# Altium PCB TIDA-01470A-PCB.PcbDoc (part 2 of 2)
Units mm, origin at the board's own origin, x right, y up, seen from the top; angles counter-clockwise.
Board outline 75 x 58 mm, 6 copper layers (Top Copper, Copper Layer 2, Copper Layer 3, Copper Layer 4, Copper Layer 5, Bottom Copper), stack 1.56 mm thick; 131 components, 70 nets, 308 pads, 94 vias.
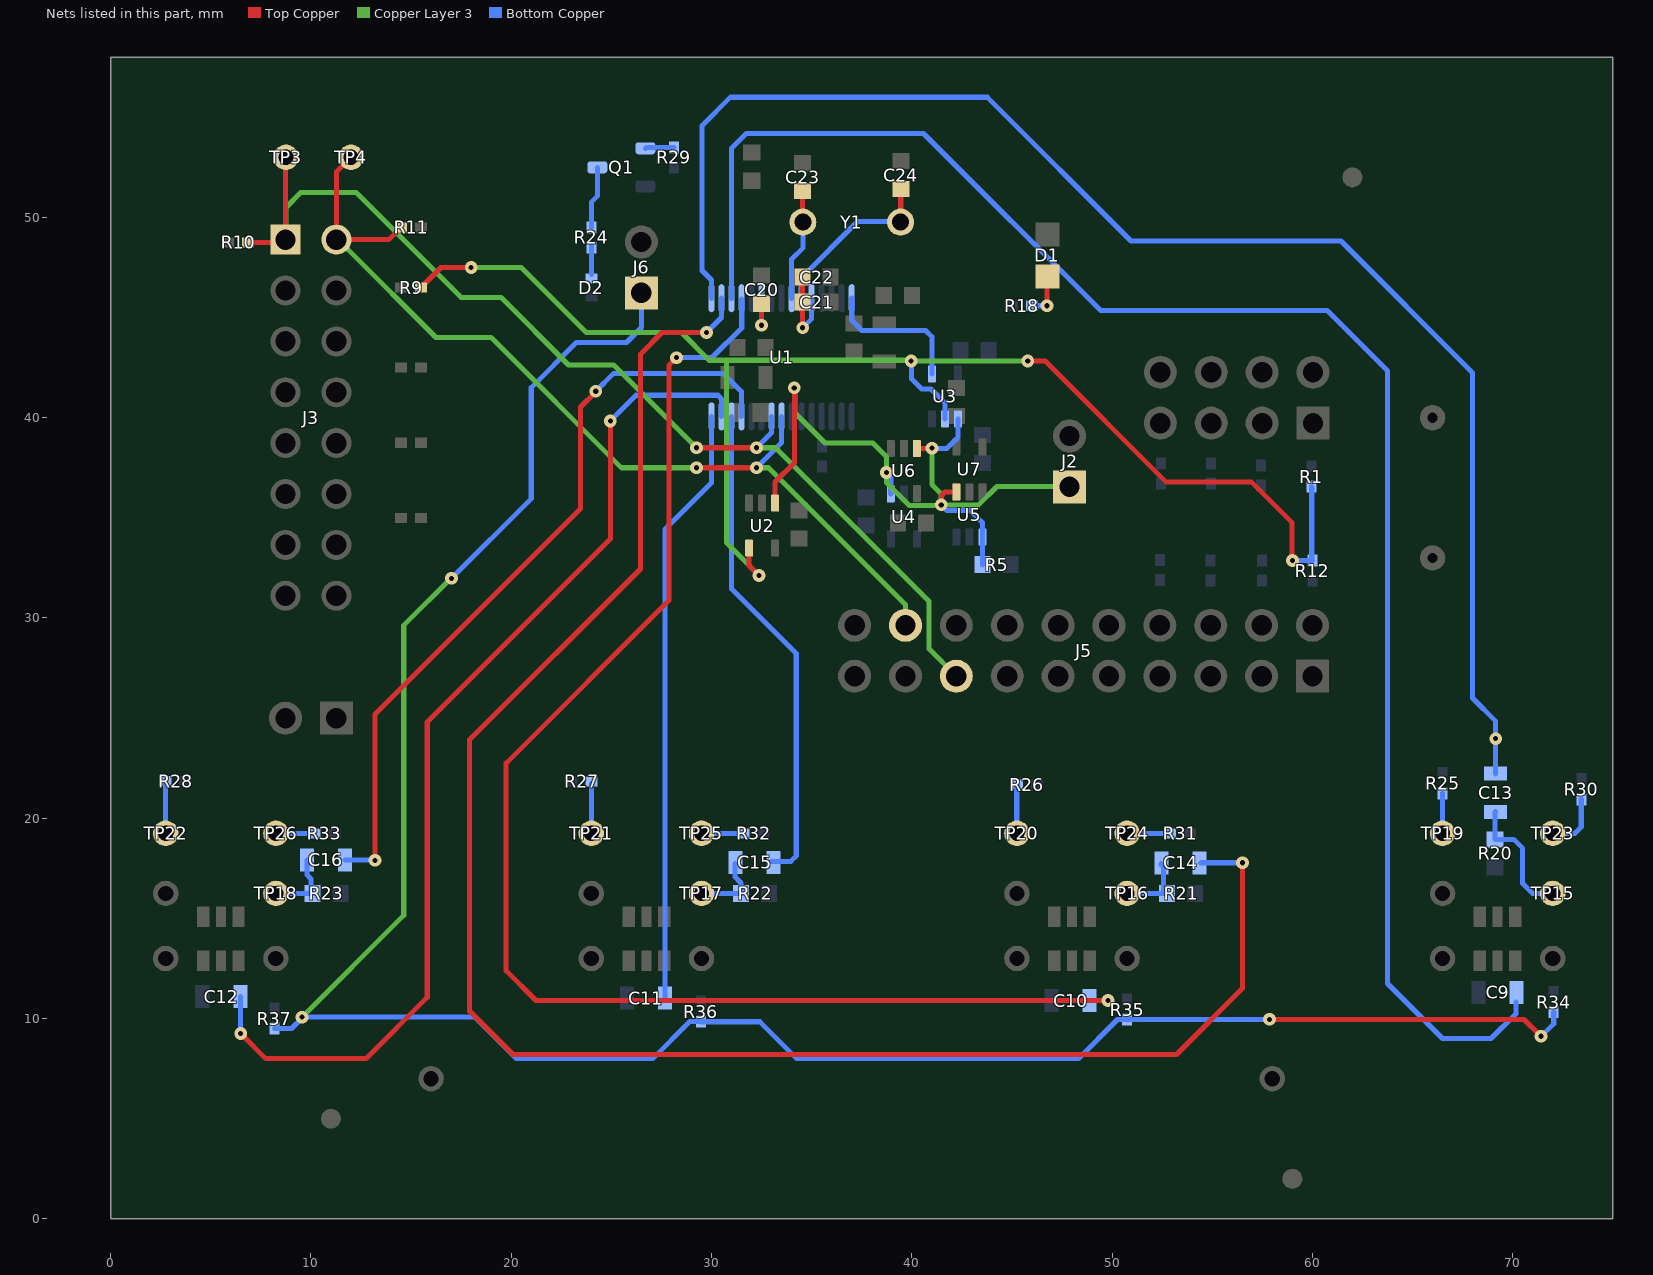
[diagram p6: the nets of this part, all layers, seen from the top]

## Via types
v1: diameter 0.635, hole 0.254, Top Copper to Bottom Copper, tented both sides, 86 vias
v2: diameter 6, hole 3.25, Top Copper to Bottom Copper, tented both sides, 4 vias
v3: diameter 0.762, hole 0.381, Top Copper to Bottom Copper, tented both sides, 4 vias

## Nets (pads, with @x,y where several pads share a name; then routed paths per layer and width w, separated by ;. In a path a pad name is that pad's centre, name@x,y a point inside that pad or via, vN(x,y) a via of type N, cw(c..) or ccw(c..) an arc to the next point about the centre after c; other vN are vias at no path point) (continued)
NetC13_2: C13.2 R20.1 TP15.1 | length 6.4
  Bottom Copper w0.254: C13.2@69.15,20.325 69.125,20.3 R20.1@69.125,18.95 70.05,18.95 70.5,18.5 70.5,16.75 71,16.25 TP15.1@72,16.25
NetC14_2: C14.2 R21.1 TP16.1 | length 3.6
  Bottom Copper w0.254: TP16.1@50.725,16.2 50.775,16.25 R21.1@52.75,16.25 52.575,16.425 C14.2@52.575,17.675 ; C14.2@52.45,17.675 C14.2@52.45,17.75
NetC15_2: C15.2 R22.1 TP17.1 | length 3.7
  Bottom Copper w0.254: TP17.1@29.45,16.225 29.475,16.25 TP17.1@29.5,16.25 R22.1@31.475,16.25 31.475,16.775 31.175,17.075 C15.2@31.175,17.75
NetC16_2: C16.2 R23.1 TP18.1 | length 3.6
  Bottom Copper w0.254: TP18.1@8.25,16.2 8.3,16.25 R23.1@10.075,16.25 ; C16.2@9.8,17.925 9.8,17.175 10,16.975 R23.1@10,16.275
NetC20_1: C20.1 U1.6 | length 2.4
  Top Copper w0.254: v1@32.5,44.64 C20.1@32.5,45.69
  Bottom Copper w0.254: v1(32.5,44.615) U1.6@32.5,45.965
NetC21_2: C21.2 C22.1 U1.11 | length 4.1
  Top Copper w0.254: v1@34.55,44.515 C21.2@34.55,45.765 ; C21.2@34.55,45.815 C22.1@34.55,47.015
  Bottom Copper w0.254: v1(34.55,44.49) 35,44.94 U1.11@35,45.965
NetC23_1: C23.1 U1.9 Y1.1 | length 5.6
  Top Copper w0.254: Y1.1@34.55,49.815 C23.1@34.55,51.315
  Bottom Copper w0.254: U1.9@34.023,45.988 U1.9@34,45.965 34,47.91 34.575,48.485 Y1.1@34.575,49.74 ; Y1.1@34.55,49.765 Y1.1@34.575,49.74 ; Y1.1@34.55,49.79 34.575,49.765 Y1.1@34.575,49.74
NetC24_1: C24.1 U1.10 Y1.2 | length 8.8
  Top Copper w0.254: Y1.2@39.45,49.715 C24.1@39.45,51.415
  Bottom Copper w0.254: U1.10@34.5,45.965 34.5,47 37.29,49.79 Y1.2@39.425,49.79
NetD1_1: D1.1 R18.1 | length 2
  Top Copper w0.254: v1(46.75,45.59) D1.1@46.75,47.09
  Bottom Copper w0.254: R18.1@46.25,45.59 v1(46.75,45.59)
NetD2_2: D2.2 R24.1 | length 1.5
  Bottom Copper w0.254: D2.2@24,47.15 R24.1@24,48.65
NetJ2_1: J2.1 R5.1 U2.1 U3.1 U4.1 U5.1 U6.1 U7.1 | length 37.2
  Top Copper w0.254: U2.1@33.175,35.74 33.175,36.785 34.15,37.76 v1@34.15,41.5 ; U6.1@40.25,38.465 v1@40.935,38.465 ; v1@41.48,35.63 41.48,36.12 41.65,36.29 U7.1@42.225,36.29
  Copper Layer 3 w0.254: v1(34.13,41.49) 34.13,41.479 34.17,41.439 34.17,40.24 35.67,38.74 38.05,38.74 38.73,38.06 38.73,36.76 39.87,35.62 v1@41.42,35.62 ; v1@41,38.46 41,36.66 41.47,36.19 v1(41.47,35.65) 43.34,35.65 44.25,36.56 J2.1@47.83,36.56
  Bottom Copper w0.254: v1@38.72,37.25 38.95,37.02 U4.1@38.95,36.19 ; v1@41.03,38.47 41.76,38.47 42.3,39.01 U3.1@42.3,39.94 ; v1@41.48,35.64 41.76,35.36 42.92,35.36 43.525,34.755 U5.1@43.525,34.04 43.525,32.645 R5.1@43.53,32.64
  other v1: 38.73,37.26 41.01,38.48
NetJ6_1: J6.1 R34.1 R35.1 R36.1 R37.1 | length 112.8
  Top Copper w0.254: v1(57.86,9.96) 70.57,9.96 v1(71.41,9.12)
  Copper Layer 3 w0.254: v1(9.55,10.07) 14.634,15.154 14.634,29.634 v1@17,32
  Bottom Copper w0.254: R37.1@8.175,9.5 9.03,9.5 v1@9.54,10.01 ; v1(9.55,10.07) 18.18,10.07 20.25,8 27.07,8 28.92,9.85 R36.1@29.39,9.85 ; v1(17.02,31.98) 21,35.96 21,41.5 23.25,43.75 25.75,43.75 26.5,44.5 J6.1@26.5,46 ; R36.1@29.47,9.84 32.41,9.84 34.25,8 48.32,8 50.27,9.95 R35.1@50.75,9.95 R35.1@50.79,9.95 ; R35.1@50.78,9.94 R35.1@50.79,9.95 ; v1(57.86,9.96) 50.8,9.96 R35.1@50.79,9.95 ; v1@71.43,9.12 72.05,9.74 R34.1@72.05,10.32 ; R34.1@72.03,10.32 R34.1@72.04,10.31
NetQ1_1: Q1.1 R29.1 | length 1.4
  Bottom Copper w0.254: Q1.1@26.7,53.45 26.75,53.5 R29.1@28.125,53.5
NetQ1_3: Q1.3 R24.2 | length 3.1
  Bottom Copper w0.254: R24.2@24,49.5 24,50.76 24.3,51.06 Q1.3@24.3,52.5
NetR25_2: R25.2 TP19.1 | length 2.1
  Bottom Copper w0.254: TP19.1@66.475,19.3 66.525,19.25 TP19.1@66.525,19.175 ; TP19.1@66.5,19.25 R25.2@66.5,21.25
NetR26_2: R26.2 TP20.1 | length 2.5
  Bottom Copper w0.254: TP20.1@45.175,19.25 45.24,19.315 45.24,21.665 R26.2@45.25,21.675
NetR27_2: R27.2 TP21.1 | length 2.4
  Bottom Copper w0.254: TP21.1@23.95,19.325 24,19.375 R27.2@24,21.75
NetR28_2: R28.2 TP22.1 | length 2.6
  Bottom Copper w0.254: R28.2@2.75,21.85 2.75,19.3 TP22.1@2.775,19.275
NetR30_2: R30.2 TP23.1 | length 2.9
  Bottom Copper w0.254: TP23.1@72.05,19.25 73.11,19.25 73.425,19.565 R30.2@73.425,20.95
NetR31_2: R31.2 TP24.1 | length 2.2
  Bottom Copper w0.254: TP24.1@50.725,19.25 TP24.1@50.75,19.25 R31.2@52.9,19.25
NetR32_2: R32.2 TP25.1 | length 2.1
  Bottom Copper w0.254: TP25.1@29.5,19.225 29.525,19.25 R32.2@31.6,19.25
NetR33_2: R33.2 TP26.1 | length 1.9
  Bottom Copper w0.254: TP26.1@8.25,19.25 10.125,19.25 R33.2@10.15,19.225
SCK: R1.1 R9.1 R12.1 U2.4 U3.2 | length 72.4
  Top Copper w0.254: R9.1@15.5,46.5 16.5,47.5 v1(18,47.5) ; U2.4@31.875,33.49 31.875,32.605 v1@32.34,32.14 ; v1@45.8,42.83 46.66,42.83 52.71,36.78 56.97,36.78 58.99,34.76 58.99,32.89 v1(59.01,32.87)
  Copper Layer 3 w0.254: v1(18,47.5) 20.5,47.5 23.75,44.25 28.5,44.25 29.88,42.87 30.75,42.87 ; v1@32.29,32.2 32.29,32.22 30.75,33.76 30.75,42.87 ; v1@39.91,42.85 39.89,42.87 30.75,42.87 ; v1(39.97,42.83) v1(45.79,42.83)
  Bottom Copper w0.254: v1@39.99,42.79 39.99,41.94 40.492,41.438 40.962,41.438 41.65,40.75 U3.2@41.65,39.94 ; v1@58.995,32.865 R12.1@59.955,32.865 ; R1.1@59.955,36.56 59.97,36.545 59.97,32.865 R12.1@60,32.865
  other v1: 32.37,32.12
SCKIA: U1.15 U3.4 | length 7.3
  Bottom Copper w0.254: U1.15@37,45.965 37,44.86 37.5,44.36 40.68,44.36 41,44.04 U3.4@41,42.19
SCL: J3.1 J5.15 R10.2 TP3.1 U1.24 | length 54.2
  Top Copper w0.254: R10.2@6.87,48.75 J3.1@8.35,48.75 ; J3.1@8.73,48.89 8.73,52.98 TP3.1@8.75,53 ; TP3.1@9,53 TP3.1@9.02,53.02 ; v1(29.25,38.5) 30.75,38.5 v1(32.25,38.5)
  Copper Layer 3 w0.254: J3.1@8.75,49 8.75,50.5 9.5,51.25 12.25,51.25 17.5,46 19.5,46 22.866,42.634 25.116,42.634 v1(29.25,38.5) ; v1(32.25,38.5) 33.2,38.5 40.86,30.84 40.86,28.46 J5.15@42.225,27.095
  Bottom Copper w0.254: v1(32.25,38.5) 33,39.25 33,39.5 U1.24@33,40.065
SDA: J3.2 J5.18 R11.2 TP4.1 U1.23 | length 47.1
  Top Copper w0.254: J3.2@11.27,48.89 11.27,52.27 TP4.1@12,53 ; J3.2@11.5,48.75 11.64,48.89 13.89,48.89 R11.2@14.5,49.5 ; TP4.1@12.25,53 TP4.1@12.27,52.98 ; v1(29.25,37.5) v1(32.25,37.5)
  Copper Layer 3 w0.254: J3.2@11.815,48.435 16.25,44 19,44 25.5,37.5 v1(29.25,37.5) ; v1(32.25,37.5) 32.85,37.5 39.685,30.665 J5.18@39.685,29.635
  Bottom Copper w0.254: v1(32.25,37.5) 33.5,38.75 U1.23@33.5,40.065
VIN1M: C13.1 U1.1 | length 74.2
  Copper Layer 3 w0.254: v1@69.07,23.91 v1@69.12,23.96 ; v1@69.1,23.925 v1@69.125,23.95
  Bottom Copper w0.254: U1.1@30,45.965 30,46.87 29.52,47.35 29.52,54.58 30.94,56 43.77,56 50.95,48.82 61.43,48.82 68,42.25 68,26 69.15,24.85 v1(69.15,23.975) C13.1@69.15,22.225
VIN1P: C9.1 U1.3 | length 84.7
  Bottom Copper w0.254: U1.3@31,45.965 31,53.45 31.74,54.19 40.59,54.19 49.43,45.35 60.74,45.35 63.75,42.34 63.75,11.75 66.5,9 68.92,9 70.16,10.24 70.16,10.81 C9.1@70.175,10.825
VIN2M: C14.1 U1.2 | length 91.1
  Top Copper w0.254: v1(29.75,44.25) 27.53,44.25 26.45,43.17 26.45,32.45 17.92,23.92 17.92,10.38 20.09,8.21 53.21,8.21 56.51,11.51 v1(56.51,17.78)
  Bottom Copper w0.254: v1@29.899,44.399 30.5,45 U1.2@30.5,45.965 ; C14.1@54.41,17.76 54.43,17.78 v1(56.51,17.78)
VIN2P: C10.1 U1.4 | length 70.9
  Top Copper w0.254: v1(28.25,43) 27.87,42.62 27.87,30.87 19.75,22.75 19.75,12.39 21.24,10.9 v1(49.8,10.9)
  Bottom Copper w0.254: v1(28.25,43) 30.03,43 31.51,44.48 31.51,45.91 U1.4@31.49,45.93 ; C10.1@48.875,10.9 v1@49.69,10.9
VIN3M: C15.1 U1.28 | length 24.6
  Bottom Copper w0.254: U1.28@31,40.065 31,31.456 34.23,28.226 34.23,18.12 33.96,17.85 C15.1@32.99,17.85
VIN3P: C11.1 U1.30 | length 30
  Bottom Copper w0.254: C11.1@27.675,11.025 27.675,34.425 30,36.75 U1.30@30,40.05
VIN4M: C16.1 U1.27 | length 38.7
  Top Copper w0.254: v1(13.2,17.9) 13.2,25.2 23.46,35.46 23.46,40.53 24.23,41.3 v1@24.23,41.33
  Bottom Copper w0.254: C16.1@11.7,17.925 v1@13.13,17.92 ; v1@24.23,41.33 25.1,42.2 30.6,42.2 31.5,41.3 31.5,40.88 U1.27@31.5,40.065 U1.27@31.477,40.088
  other v1: 24.22,41.32
VIN4P: C12.1 U1.29 | length 52.5
  Top Copper w0.254: v1@6.56,9.19 7.75,8 12.75,8 15.81,11.06 15.81,24.81 24.95,33.95 v1(24.95,39.84)
  Bottom Copper w0.254: C12.1@6.475,11.1 6.475,9.285 v1@6.51,9.25 ; v1(24.95,39.84) 26.23,41.12 30.32,41.12 30.5,40.94 U1.29@30.5,40.065
  other v1: 6.49,9.25
pads on no net: FID1.1 FID2.1 FID3.1 H1.0 H2.0 H3.0 H4.0 H5.0 H6.0 H7.0 H8.0 J3.5 J3.13 J3.14 SH1.0 SH2.0 U1.26

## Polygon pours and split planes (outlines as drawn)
GND on Copper Layer 5 "GND2" (solid, remove dead copper, pour order 38): 0,0 0,58 75,58 75,0
GND on Copper Layer 4 "COPPER_LAYER_4_GND_P042" (solid, remove dead copper, pour order 42): 0,0 0,58 75,58 75,0
3.3V on Copper Layer 4 "3.3V" (solid, remove dead copper, pour order 40): 68,12 65,9 8.575,9 4.5,13.075 4.5,50.333 5.667,51.5 20,51.5 25,56.5 55.5,56.5 68,44
GND on Bottom Copper "BOTTOM_COPPER_GND_P044" (solid, remove dead copper, pour order 44): 0,0 0,58 75,58 75,0
GND on Top Copper "TOP_COPPER_GND_P046" (solid, remove dead copper, pour order 46): 0,0 0,58 75,58 75,0
GND on Copper Layer 3 "COPPER_LAYER_3_GND_P048" (solid, remove dead copper, pour order 48): 0,0 0,58 75,58 75,-0.18 74.82,0
GND on Copper Layer 2 "GND1" (solid, remove dead copper, pour order 50): 75,58 75,0 0,0 0,58

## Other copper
Top Copper:
  text ".Layer_Name" at 2.156,-34.306 h1.52
Copper Layer 2:
  text ".Layer_Name" at 2.156,-34.306 h1.52
Copper Layer 3:
  text ".Layer_Name" at 2.156,-34.306 h1.52
Copper Layer 4:
  text ".Layer_Name" at 2.156,-34.306 h1.52
Copper Layer 5:
  text ".Layer_Name" at 2,-34.25 h1.52
Bottom Copper:
  text ".Layer_Name" at 2.156,-34.306 h1.52

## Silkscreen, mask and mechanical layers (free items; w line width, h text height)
Top SilkScreen:
  circle w0.254: c19,54 r3.25
  circle w0.254: c71,4 r3.25
  circle w0.254: c71,54 r3.25
  circle w0.254: c4,4 r3.25
  lines w0.2: 36.875,25.375 37.625,25.375 ; 37,25.125 37.5,25.125 ; 37.125,24.875 37.375,24.875 ; 37.25,25.375 37.25,25.75 ; 39.375,25.375 40.125,25.375 ; 39.5,25.125 40,25.125 ; 39.625,24.875 39.875,24.875 ; 39.75,25.375 39.75,25.75 ; 44.375,25.375 45.125,25.375 ; 44.375,31.625 45.125,31.625 ; 44.5,25.125 45,25.125 ; 44.5,31.375 45,31.375 ; 44.625,24.875 44.875,24.875 ; 44.625,31.125 44.875,31.125 ; 44.75,25.375 44.75,25.75 ; 44.75,31.625 44.75,32 ; 46.875,25.375 47.625,25.375 ; 47,25.125 47.5,25.125 ; 47.125,24.875 47.375,24.875 ; 47.25,25.375 47.25,25.75 ; 49.375,25.375 50.125,25.375 ; 49.375,31.625 50.125,31.625 ; 49.5,25.125 50,25.125 ; 49.5,31.375 50,31.375 ; 49.625,24.875 49.875,24.875 ; 49.625,31.125 49.875,31.125 ; 49.75,25.375 49.75,25.75 ; 49.75,31.625 49.75,32 ; 52.125,25.375 52.875,25.375 ; 52.25,25.125 52.75,25.125 ; 52.375,24.875 52.625,24.875 ; 52.5,25.375 52.5,25.75 ; 54.625,25.375 55.375,25.375 ; 54.75,25.125 55.25,25.125 ; 54.875,24.875 55.125,24.875 ; 55,25.375 55,25.75 ; 57.125,25.375 57.875,25.375 ; 57.25,25.125 57.75,25.125 ; 57.375,24.875 57.625,24.875 ; 57.5,25.375 57.5,25.75 ; 59.625,25.375 60.375,25.375 ; 59.75,25.125 60.25,25.125 ; 59.875,24.875 60.125,24.875 ; 60,25.375 60,25.75
  text "INTA" at 37.75,31 h1 r90
  text "SDA" at 40.25,31 h1 r90
  text "3.3V" at 42.75,31 h1 r90
  text "DATA3" at 47.75,31 h1 r90
  text "DATA1" at 53,31 h1 r90
  text "LRCLK" at 55.5,31 h1 r90
  text "BCLK" at 58,31 h1 r90
  text "MCLK" at 60.5,31 h1 r90
  text "'.EVM_Orderable'" at 12.5,27.5 h2
  text "'.PRJ_Number' '.PCB_Rev'" at 15.75,25 h1.6
  text "SCL" at 42.75,23.25 h1 r90
  text ".Layer_Name" at 2.156,-34.306 h1.52
Bottom Silk:
  lines w0.2: 36.875,25 37.625,25 ; 37,24.75 37.5,24.75 ; 37.125,24.5 37.375,24.5 ; 37.25,25 37.25,25.375 ; 39.375,25 40.125,25 ; 39.5,24.75 40,24.75 ; 39.625,24.5 39.875,24.5 ; 39.75,25 39.75,25.375 ; 44.375,25 45.125,25 ; 44.375,31.81 45.125,31.81 ; 44.5,24.75 45,24.75 ; 44.5,31.56 45,31.56 ; 44.625,24.5 44.875,24.5 ; 44.625,31.31 44.875,31.31 ; 44.75,25 44.75,25.375 ; 44.75,31.81 44.75,32 ; 46.875,25 47.625,25 ; 47,24.75 47.5,24.75 ; 47.125,24.5 47.375,24.5 ; 47.25,25 47.25,25.375 ; 49.375,25 50.125,25 ; 49.375,31.875 50.125,31.875 ; 49.5,24.75 50,24.75 ; 49.5,31.625 50,31.625 ; 49.625,24.5 49.875,24.5 ; 49.625,31.375 49.875,31.375 ; 49.75,25 49.75,25.375 ; 49.75,31.875 49.75,32.25 ; 52.125,25 52.875,25 ; 52.25,24.75 52.75,24.75 ; 52.375,24.5 52.625,24.5 ; 52.5,25 52.5,25.375 ; 54.625,25 55.375,25 ; 54.75,24.75 55.25,24.75 ; 54.875,24.5 55.125,24.5 ; 55,25 55,25.375 ; 57.125,25 57.875,25 ; 57.25,24.75 57.75,24.75 ; 57.375,24.5 57.625,24.5 ; 57.5,25 57.5,25.375 ; 59.625,25 60.375,25 ; 59.75,24.75 60.25,24.75 ; 59.875,24.5 60.125,24.5 ; 60,25 60,25.375
  text "GND" at 57.5,44.25 h1
  text "MASTER/ / SLAVE" at 50.5,40.875 h0.8
  text "2" at 63.25,40.125 h0.5
  text "I S" at 63.625,39.5 h1
  text "DATA1" at 51.5,38 h0.75 r90
  text "LRCLK" at 54,38 h0.75 r90
  text "BCLK" at 56.75,38 h0.75 r90
  text "MCLK" at 59.25,38 h0.75 r90
  text "DATA3" at 47.5,34 h0.6 r90
  text "LRCLK" at 54.375,33.75 h0.6 r90
  text "DATA" at 51.75,33.5 h0.6 r90
  text "BCLK" at 57,33.5 h0.6 r90
  text "MCLK" at 59.5,33.5 h0.6 r90
  text "3.3V" at 42.5,33.365 h0.75 r90
  text "INTA" at 37.5,33.25 h0.75 r90
  text "SDA" at 40,33.25 h0.75 r90
  text "SCL" at 42.75,25.36 h0.75 r90
  text ".Layer_Name" at 2.156,-34.306 h1.52
Top Paste:
  text ".Layer_Name" at 2.156,-34.306 h1.52
Bottom Paste:
  text ".Layer_Name" at 2.156,-34.306 h1.52
Top Solder Mask:
  text ".Layer_Name" at 2.156,-34.306 h1.52
Bottom Solder Mask:
  text ".Layer_Name" at 2.156,-34.306 h1.52
Drill Guide:
  text ".Layer_Name" at 82.5,25 h1.52
M1 Board Outline:
  the board outline again, w0.25
  text ".Layer_Name" at 44.25,-34.75 h1.52
M2 Board Dimensions:
  text ".Layer_Name" at 69.75,-34.75 h1.52
M3 3D STEP Top:
  text ".Layer_Name" at 2.156,-34.306 h1.52
M4 3D STEP Bottom:
  text ".Layer_Name" at 2.156,-34.306 h1.52
M5 Assembly Top:
  lines w0.254: -19.917,-36.126 147.723,-36.126 ; -19.917,-30.962 147.774,-30.962 ; -19.917,-25.797 -19.917,-41.291 81.81,-41.291 147.774,-41.291 147.774,-25.797 -19.904,-25.797 -19.904,-41.291 20.114,-41.291 ; 42.694,-41.291 42.694,-25.797 ; 74.876,-30.962 74.876,-25.797 ; 96.212,-30.962 96.212,-25.797 ; 112.011,-41.456 112.011,-36.304
  text "PCB VIEWED FROM TOP SIDE" at -18.304,-29.154 h1.52
  text "BOARD #:" at 44.599,-29.154 h1.52
  text ".PRJ_Number" at 58.455,-29.154 h1.52
  text "REV:" at 79.905,-29.154 h1.52
  text ".PCB_Rev" at 87.309,-29.154 h1.52
  text "SVN REV:" at 101.19,-29.154 h1.52
  text ".VersionControl_RevNumber" at 114.043,-29.154 h1.52
  text "PLOT NAME =" at -18.304,-39.534 h1.52
  text ".plot_File_Name" at 2.156,-39.534 h1.52
  text "GENERATED    :" at 44.65,-39.534 h1.52
  text ".Print_Date" at 66.735,-39.534 h1.52
  text ".Print_Time" at 85.252,-39.534 h1.52
  text "TEXAS INSTRUMENTS" at 117.37,-39.534 h1.52
M6 Assembly Bottom:
  lines w0.254: -19.93,-30.974 147.761,-30.974 ; -19.879,-36.139 147.761,-36.139 ; 15.834,-41.469 15.834,-36.317 ; 31.632,-30.974 31.632,-25.81 ; 52.968,-30.974 52.968,-25.81 ; 85.15,-41.304 85.15,-25.81 ; 107.731,-41.304 147.749,-41.304 147.749,-25.81 -19.93,-25.81 -19.93,-41.304 46.034,-41.304 147.761,-41.304 147.761,-25.81
  text ".VersionControl_RevNumber" at 13.802,-29.167 h1.52
  text "SVN REV:" at 26.654,-29.167 h1.52
  text ".PCB_Rev" at 40.535,-29.167 h1.52
  text "REV:" at 47.939,-29.167 h1.52
  text ".PRJ_Number" at 69.39,-29.167 h1.52
  text "BOARD #:" at 83.245,-29.167 h1.52
  text "PCB VIEWED FROM BOTTOM SIDE" at 146.148,-29.167 h1.52
  text "TEXAS INSTRUMENTS" at 10.474,-39.547 h1.52
  text ".Print_Time" at 42.593,-39.547 h1.52
  text ".Print_Date" at 61.109,-39.547 h1.52
  text "GENERATED    :" at 83.194,-39.547 h1.52
  text ".plot_File_Name" at 125.689,-39.547 h1.52
  text "PLOT NAME =" at 146.148,-39.547 h1.52
M9 Title Sheet:
  drawing of 57 lines, arcs and shapes, not listed
  text "1" at 6.292,191.627 h1.78
  text "2" at 69.682,191.627 h1.78
  text "3" at 132.911,191.627 h1.78
  text "4" at 196.58,191.627 h1.78
  text "5" at 260.055,191.627 h1.78
  text "6" at 323.682,191.627 h1.78
  text "A" at -23.079,162.595 h1.78
  text "A" at 352.841,162.595 h1.78
  text "B" at -23.079,102.143 h1.78
  text "B" at 352.841,102.143 h1.78
  text "C" at -23.079,41.818 h1.78
  text "C" at 352.841,41.818 h1.78
  text "PROJECT TITLE:" at 275.625,-5.452 h1.14
  text ".PRJ_Title" at 276.895,-8.838 h1.78
  text "DESIGNED FOR:" at 275.625,-13.097 h1.14
  text ".PRJ_Customer" at 276.895,-16.653 h1.78
  text "D" at -23.079,-18.38 h1.78
  text "D" at 352.841,-18.38 h1.78
  text "FILE NAME:" at 275.625,-20.717 h1.14
  text ".PCB_File_Name_No_Path" at 276.895,-23.765 h1.78
  text "Texas Instruments (TI) and/or its licensors do not warrant the accuracy or completeness of this specification" at 149.4,-27.876 h1.14
  text "ENGINEER:" at 275.625,-28.083 h1.14
  text "LAYOUT BY:" at 313.852,-28.083 h1.14
  text "or any information contained therein. TI and/or its licensors do not warrant that this design will meet" at 148.257,-30.737 h1.14
  text ".PRJ_Engineer" at 276.895,-32.02 h1.78
  text ".PCB_Layout" at 315.135,-32.02 h1.78
  text "the specifications, will be suitable for your application or fit for any particular purpose, or will operate in" at 148.257,-33.599 h1.14
  text "ALTIUM DESIGNER VERSION:" at 313.852,-35.957 h1.14
  text "an implementation. TI and/or its licensors do not warrant that the design is production worthy. You should" at 148.257,-36.461 h1.14
  text "completely validate and test your design implementation to confirm the system functionality for your application." at 149.4,-39.322 h1.14
  text ".print_Scale" at 276.895,-39.343 h1.78
  text ".Application_BuildNumber" at 315.135,-39.343 h1.78
  text "1" at 6.292,-44.593 h1.78
  text "2" at 69.682,-44.593 h1.78
  text "3" at 132.911,-44.593 h1.78
  text "4" at 196.58,-44.593 h1.78
  text "5" at 260.055,-44.593 h1.78
  text "6" at 323.682,-44.593 h1.78
M10 Fab Notes:
  drawing of 188 lines, arcs and shapes, not listed
  text ".Layer_Name" at 274.769,186.785 h1.52
  text "SPECIAL NOTES" at 302.519,182.285 h2
  text "THE MICROPHONES USED IN THIS BOARD REQUIRE SPECIAL SOLDERING CONSIERATIONS:" at 275.519,175.535 h1.52
  text "MSL (MOISTURE SENSITIVITY LEVEL) CLASS 1. / MAXIMUM OF 3 REFLOW CYCLES IS RECOMMENDED. / DO NOT EXPOSE THE MICROPHONES TO TEMP EXCEEDING 260 C / DO NOT BOARD WASH OR CLEAN AFTER THE REFLOW PROCESS. / DO NOT BRUSH BOARD WITH OR WITHOUT SOLVENTS AFTER THE REFLOW PROCESS. / DO NOT DIRECTLY EXPOSE TO ULTRASONIC PROCESSING, WELDING, OR CLEANING. / DO NOT APPLY OVER 30 PSI OF AIR PRESSURE INTO THE PORT HOLE." at 279.894,149.66 h1.52
  text "DESIGN INFORMATION" at 301.921,145.04 h1.52
  text "DESIGN INFORMATION" at 301.902,145.005 h1.52
  text "MIN. TRACK WIDTH:" at 285.53,140.433 h1.52
  text "8" at 313.374,140.433 h1.52
  text "MIL" at 317.305,140.433 h1.52
  text "MIN. CLEARANCE:" at 285.53,137.081 h1.52
  text "0.2" at 311.85,137.081 h1.52
  text "mm" at 317.305,137.081 h1.52
  text "MIN. VIA PAD SIZE:" at 285.53,133.728 h1.52
  text "24" at 312.613,133.728 h1.52
  text "MIL" at 317.305,133.728 h1.52
  text "0.05mm (2MIL)" at 303.183,130.128 h1.52
  text "MINIMUM ANNULAR RING" at 277.167,130.02 h1.52
  text "EXTERNAL" at 321.166,130.02 h1.52
  text "PER" at 282.247,127.022 h1.52
  text "IPC-D-275 CLASS 2 LEVEL C" at 287.835,127.022 h1.52
  text "MIL, HOLES" at 325.636,124.17 h1.52
  text "+/-" at 315.668,124.152 h1.52
  text "+/-" at 337.36,124.152 h1.52
  text "REGISTRATION TOLERANCES:" at 277.167,124.025 h1.52
  text "METAL" at 307.642,124.025 h1.52
  text "5" at 322.277,124.025 h1.52
  text "3" at 343.435,124.025 h1.52
  text "MIL" at 346.388,124.025 h1.52
  text "+/-" at 337.36,121.155 h1.52
  text "HOLE SIZE TOLERANCE (UNLESS OTHERWISE SPECIFIED):" at 277.167,121.028 h1.52
  text "3" at 343.435,121.028 h1.52
  text "MIL" at 346.388,121.028 h1.52
  text "MATERIAL:" at 275.268,115.708 h1.52
  text "FR-4 High Tg" at 300.324,112.143 h1.52
  text "FR-408" at 285.962,111.925 h1.52
  text "OTHER" at 323.757,111.925 h1.52
  text "X" at 296.389,111.833 h1.52
  text "62 MIL (1.6mm) +/-10%" at 294.092,107.792 h1.52
  text "THICKNESS:" at 277.167,107.684 h1.52
  text "X" at 290.837,107.684 h1.52
  text "OTHER" at 326.729,107.684 h1.52
  text "TOLERANCE:" at 277.167,103.67 h1.52
  text "X" at 298.486,103.67 h1.52
  text "ANSI IPC-6012 TYPE 3 CLASS 2" at 303.234,103.67 h1.52
  text "OTHER +/-" at 303.234,99.708 h1.52
  text "BOW & TWIST:" at 277.167,95.72 h1.52
  text "X" at 298.486,95.72 h1.52
  text "ANSI IPC-6012 TYPE 3 CLASS 2" at 303.234,95.72 h1.52
  text "OTHER +/-" at 303.234,91.694 h1.52
  text "DRILLING:" at 275.268,88.176 h1.52
  text "REFERENCE:" at 277.167,85.205 h1.52
  text "X" at 293.632,85.205 h1.52
  text "AS SHOWN" at 298.382,85.205 h1.52
  text "X" at 316.518,85.205 h1.52
  text "NC_DRILL FILES" at 319.998,85.205 h1.52
  text "PTH COPPER THICKNESS:" at 277.167,81.191 h1.52
  text "X" at 305.875,81.191 h1.52
  text "20-30 um" at 309.355,81.191 h1.52
  text "OTHER" at 327.567,81.191 h1.52
  text "BOARD FINISH:" at 275.268,77.153 h1.52
  text "SILKSCREEN:" at 279.211,74.156 h1.52
  text "X" at 303.31,74.156 h1.52
  text "TOP" at 306.51,74.156 h1.52
  text "X" at 316.264,74.156 h1.52
  text "BOTTOM" at 319.49,74.156 h1.52
  text "SILKSCREEN COLOR:" at 279.211,69.914 h1.52
  text "X" at 303.283,69.914 h1.52
  text "WHITE" at 306.51,69.914 h1.52
  text "OTHER" at 319.49,69.914 h1.52
  text "X" at 306.611,65.87 h1.52
  text "GREEN" at 309.838,65.87 h1.52
  text "OTHER" at 325.535,65.87 h1.52
  text "SOLDER RESIST COLOR:" at 279.211,65.596 h1.52
  text "X" at 306.611,61.552 h1.52
  text "MATTE" at 309.838,61.552 h1.52
  text "SEMI-GLOSS" at 325.523,61.536 h1.52
  text "IMMERSION GOLD (ENIG)" at 302.218,56.764 h1.52
  text "ENEPIG" at 336.191,56.68 h1.52
  text "SURFACE FINISH:" at 275.268,56.655 h1.52
  text "X" at 297.469,56.655 h1.52
  text "IMM. TIN/SILVER OR EQUIV" at 283.639,52.667 h1.52
  text "OTHER" at 319.998,52.667 h1.52
  text "ARRAY/PANEL:" at 275.268,48.121 h1.52
  text "CUT AND TRIM PER M1 BOARD OUTLINE" at 302.218,48.012 h1.52
  text "N.C. ROUTE" at 302.218,44.158 h1.52
  text "X" at 319.464,44.158 h1.52
  text "V. SCORE" at 324.214,44.158 h1.52
  text "CERTIFICATION:" at 275.268,40.678 h1.52
  text "MATERIALS AND WORKMANSHIP FOR ALL PCBS" at 293.683,40.678 h1.52
  text "TO MEET OR EXCEED THE REQUIREMENTS OF:" at 293.683,38.189 h1.52
  text "X" at 284.196,34.722 h1.52
  text "ANSI IPC-A-600F CLASS ->" at 287.727,34.722 h1.52
  text "X" at 329.359,34.722 h1.52
  text "2" at 332.38,34.722 h1.52
  text "1" at 324.379,34.684 h1.52
  text "3" at 341.372,34.684 h1.52
  text "X" at 304.873,30.671 h1.52
  text "RoHS" at 308.352,30.671 h1.52
  text "OTHER" at 324.72,30.671 h1.52
  text "PER ORDER" at 334.805,30.671 h1.52
  text "ALL BOARDS MUST MEET OR EXCEED UL94-V0 REQUIREMENTS." at 275.968,26.464 h1.52
  text "PCB MUST BEAR THE UL94V-0 UL REGISTERED MATERIAL ID NUMBER" at 275.968,23.416 h1.52
  text "ADDITIONAL REQUIREMENTS:" at 275.268,19.012 h1.52
  text "MICROSECTION:" at 277.167,16.091 h1.52
  text "YES" at 300.173,16.091 h1.52
  text "REQUIRED" at 322.055,12.125 h1.52
  text "BARE BOARD ELEC. TEST:" at 277.167,12.053 h1.52
  text "NONE" at 310.333,12.053 h1.52
  text "X" at 318.829,12.053 h1.52
  text "PER ORDER" at 337.092,12.053 h1.52
M11 Gerber Information:
  lines w0.254: -19.917,-36.126 147.723,-36.126 ; -19.917,-30.962 147.774,-30.962 ; -19.917,-25.797 -19.917,-41.291 81.81,-41.291 147.774,-41.291 147.774,-25.797 -19.904,-25.797 -19.904,-41.291 20.114,-41.291 ; 42.694,-41.291 42.694,-25.797 ; 74.876,-30.962 74.876,-25.797 ; 96.212,-30.962 96.212,-25.797 ; 112.011,-41.456 112.011,-36.304
  text "ALL ARTWORK VIEWED FROM TOP SIDE" at -18.304,-29.154 h1.52
  text "BOARD #:" at 44.599,-29.154 h1.52
  text ".PRJ_Number" at 58.455,-29.154 h1.52
  text "REV:" at 79.905,-29.154 h1.52
  text ".PCB_Rev" at 87.309,-29.154 h1.52
  text "SVN REV:" at 101.19,-29.154 h1.52
  text ".VersionControl_RevNumber" at 114.043,-29.154 h1.52
  text "LAYER NAME =" at -18.304,-34.306 h1.52
  text "PLOT NAME =" at -18.304,-39.534 h1.52
  text ".plot_File_Name" at 2.156,-39.534 h1.52
  text "GENERATED    :" at 44.65,-39.534 h1.52
  text ".Print_Date" at 66.735,-39.534 h1.52
  text ".Print_Time" at 85.252,-39.534 h1.52
  text "TEXAS INSTRUMENTS" at 117.37,-39.534 h1.52
M12 Stackup:
  drawing of 399 lines, arcs and shapes, not listed
  text ".Layer_Name" at 105,82.5 h1.52
  text "Layer" at 106.715,76.673 h1.52
  text "Name" at 117.126,76.673 h1.52
  text "Material" at 146.582,76.673 h1.52
  text "Thickness" at 168.42,76.673 h1.52
  text "Constant" at 184.926,76.673 h1.52
  text "Board Layer Stack" at 199.4,76.673 h1.52
  text "1" at 106.715,73.625 h1.52
  text "Top SilkScreen" at 117.126,73.625 h1.52
  text "2" at 106.715,70.577 h1.52
  text "Top Solder Mask" at 117.126,70.577 h1.52
  text "Solder Resist" at 146.582,70.577 h1.52
  text "0.50mil" at 168.42,70.577 h1.52
  text "3.5" at 184.926,70.577 h1.52
  text "3" at 106.715,67.529 h1.52
  text "Top Copper" at 117.126,67.529 h1.52
  text "Copper" at 146.582,67.529 h1.52
  text "1.40mil" at 168.42,67.529 h1.52
  text "4" at 106.715,64.481 h1.52
  text "Dielectric 1" at 117.126,64.481 h1.52
  text "FR-4" at 146.582,64.481 h1.52
  text "7.00mil" at 168.42,64.481 h1.52
  text "4.2" at 184.926,64.481 h1.52
  text "5" at 106.715,61.433 h1.52
  text "Copper Layer 2" at 117.126,61.433 h1.52
  text "Copper" at 146.582,61.433 h1.52
  text "1.40mil" at 168.42,61.433 h1.52
  text "6" at 106.715,58.385 h1.52
  text "Dielectric 2" at 117.126,58.385 h1.52
  text "FR-4" at 146.582,58.385 h1.52
  text "14.00mil" at 168.42,58.385 h1.52
  text "4.2" at 184.926,58.385 h1.52
  text "7" at 106.715,55.337 h1.52
  text "Copper Layer 3" at 117.126,55.337 h1.52
  text "Copper" at 146.582,55.337 h1.52
  text "1.40mil" at 168.42,55.337 h1.52
  text "8" at 106.715,52.289 h1.52
  text "Dielectric 4" at 117.126,52.289 h1.52
  text "FR-4" at 146.582,52.289 h1.52
  text "11.00mil" at 168.42,52.289 h1.52
  text "4.2" at 184.926,52.289 h1.52
  text "9" at 106.715,49.241 h1.52
  text "Copper Layer 4" at 117.126,49.241 h1.52
  text "Copper" at 146.582,49.241 h1.52
  text "1.40mil" at 168.42,49.241 h1.52
  text "10" at 106.715,46.193 h1.52
  text "Dielectric 5" at 117.126,46.193 h1.52
  text "FR-4" at 146.582,46.193 h1.52
  text "14.00mil" at 168.42,46.193 h1.52
  text "4.2" at 184.926,46.193 h1.52
  text "11" at 106.715,43.145 h1.52
  text "Copper Layer 5" at 117.126,43.145 h1.52
  text "Copper" at 146.582,43.145 h1.52
  text "1.40mil" at 168.42,43.145 h1.52
  text "12" at 106.715,40.097 h1.52
  text "Dielectric 3" at 117.126,40.097 h1.52
  text "FR-4" at 146.582,40.097 h1.52
  text "7.00mil" at 168.42,40.097 h1.52
  text "4.2" at 184.926,40.097 h1.52
  text "13" at 106.715,37.049 h1.52
  text "Bottom Copper" at 117.126,37.049 h1.52
  text "Copper" at 146.582,37.049 h1.52
  text "1.40mil" at 168.42,37.049 h1.52
  text "14" at 106.715,34.001 h1.52
  text "Bottom Solder Mask" at 117.126,34.001 h1.52
  text "Solder Resist" at 146.582,34.001 h1.52
  text "0.50mil" at 168.42,34.001 h1.52
  text "3.5" at 184.926,34.001 h1.52
  text "15" at 106.715,30.953 h1.52
  text "Bottom Silk" at 117.126,30.953 h1.52
M13 Component Bodies Top:
  text ".Layer_Name" at 2.156,-34.306 h1.52
M14 Component Bodies Bottom:
  text ".Layer_Name" at 2.156,-34.306 h1.52
M15 Courtyards Top:
  text ".Layer_Name" at 2.156,-34.306 h1.52
M16 Courtyards Bottom:
  text ".Layer_Name" at 2.156,-34.306 h1.52
Drill Drawing:
  lines w0.22: 83.73,3.532 84.873,3.532 84.873,4.674 83.73,4.674 83.73,3.532 ; 83.73,7.244 84.873,7.244 84.301,6.102 83.73,7.244 ; 83.73,9.244 84.301,8.672 84.873,9.244 84.301,9.815 83.73,9.244 ; 83.73,11.528 84.016,11.528 84.016,11.243 84.587,11.243 84.587,11.528 84.873,11.528 84.873,12.099 84.587,12.099 84.587,12.385 84.016,12.385 84.016,12.099 83.73,12.099 83.73,11.528 ; 83.73,13.813 84.873,13.813 84.873,14.955 83.73,14.955 83.73,13.813 ; 83.73,16.669 84.016,16.669 84.301,16.383 84.587,16.669 84.873,16.669 84.587,16.954 84.873,17.24 84.587,17.24 84.301,17.526 84.016,17.24 83.73,17.24 84.016,16.954 83.73,16.669 ; 83.73,18.954 83.73,19.239 84.016,19.525 83.73,19.81 83.73,20.096 84.016,20.096 84.301,19.81 84.587,20.096 84.873,20.096 84.873,19.81 84.587,19.525 84.873,19.239 84.873,18.954 84.587,18.954 84.301,19.239 84.016,18.954 83.73,18.954 ; 83.959,3.76 84.644,3.76 84.644,4.446 83.959,4.446 83.959,3.76
  lines w0.381: 82.691,2.761 271.457,2.761 ; 82.691,20.753 271.457,20.753 ; 92.286,0.191 92.286,23.323 ; 102.49,0.191 102.49,23.323 ; 122.287,0.191 122.287,23.323 ; 131.111,0.191 131.111,23.323 ; 143.84,0.191 143.84,23.323 ; 171.688,0.191 171.688,23.323 ; 181.951,0.191 181.951,23.323 ; 194.886,0.191 194.886,23.323 ; 209.887,0.191 209.887,23.323 ; 224.672,0.191 224.672,23.323 ; 247.679,0.191 247.679,23.323 ; 82.691,0.191 271.457,0.191 271.457,23.323 82.691,23.323 82.691,0.191
  text "Symbol" at 84.233,21.524 h1.23
  text "Count" at 93.057,21.524 h1.23
  text "Hole Size" at 103.261,21.524 h1.23
  text "Plated" at 123.058,21.524 h1.23
  text "Hole Type" at 131.882,21.524 h1.23
  text "Drill Layer Pair" at 144.611,21.524 h1.23
  text "Via/Pad" at 172.459,21.524 h1.23
  text "Pad Shape" at 182.722,21.524 h1.23
  text "Template" at 195.657,21.524 h1.23
  text "Description" at 210.658,21.524 h1.23
  text "Hole Tolerance (+)" at 225.443,21.524 h1.23
  text "Hole Tolerance (-)" at 248.45,21.524 h1.23
  text "2" at 93.057,18.954 h1.03
  text "0.508mm (20.00mil)" at 103.261,18.954 h1.03
  text "PTH" at 123.058,18.954 h1.03
  text "Round" at 131.882,18.954 h1.03
  text "Top Copper - Bottom Copper" at 144.611,18.954 h1.03
  text "Pad" at 172.459,18.954 h1.03
  text "Rounded" at 182.722,18.954 h1.03
  text "c127h51" at 195.657,18.954 h1.03
  text "2" at 93.057,16.383 h1.03
  text "0.850mm (33.46mil)" at 103.261,16.383 h1.03
  text "PTH" at 123.058,16.383 h1.03
  text "Round" at 131.882,16.383 h1.03
  text "Top Copper - Bottom Copper" at 144.611,16.383 h1.03
  text "Pad" at 172.459,16.383 h1.03
  text "Rounded" at 182.722,16.383 h1.03
  text "c135h85" at 195.657,16.383 h1.03
  text "4" at 93.057,13.813 h1.03
  text "0.381mm (15.00mil)" at 103.261,13.813 h1.03
  text "PTH" at 123.058,13.813 h1.03
  text "Round" at 131.882,13.813 h1.03
  text "Top Copper - Bottom Copper" at 144.611,13.813 h1.03
  text "Via" at 172.459,13.813 h1.03
  text "Rounded" at 182.722,13.813 h1.03
  text "v76h38m0mx0" at 195.657,13.813 h1.03
  text "4" at 93.057,11.243 h1.03
  text "3.250mm (127.95mil)" at 103.261,11.243 h1.03
  text "PTH" at 123.058,11.243 h1.03
  text "Round" at 131.882,11.243 h1.03
  text "Top Copper - Bottom Copper" at 144.611,11.243 h1.03
  text "Via" at 172.459,11.243 h1.03
  text "Rounded" at 182.722,11.243 h1.03
  text "v600h325m0mx0" at 195.657,11.243 h1.03
  text "28" at 93.057,8.672 h1.03
  text "0.762mm (30.00mil)" at 103.261,8.672 h1.03
  text "PTH" at 123.058,8.672 h1.03
  text "Round" at 131.882,8.672 h1.03
  text "Top Copper - Bottom Copper" at 144.611,8.672 h1.03
  text "Pad" at 172.459,8.672 h1.03
  text "Rounded" at 182.722,8.672 h1.03
  text "c127h76" at 195.657,8.672 h1.03
  text "50" at 93.057,6.102 h1.03
  text "1.016mm (40.00mil)" at 103.261,6.102 h1.03
  text "PTH" at 123.058,6.102 h1.03
  text "Round" at 131.882,6.102 h1.03
  text "Top Copper - Bottom Copper" at 144.611,6.102 h1.03
  text "Pad" at 172.459,6.102 h1.03
  text "(Mixed)" at 182.722,6.102 h1.03
  text "(Mixed)" at 195.657,6.102 h1.03
  text "86" at 93.057,3.532 h1.03
  text "0.254mm (10.00mil)" at 103.261,3.532 h1.03
  text "PTH" at 123.058,3.532 h1.03
  text "Round" at 131.882,3.532 h1.03
  text "Top Copper - Bottom Copper" at 144.611,3.532 h1.03
  text "Via" at 172.459,3.532 h1.03
  text "Rounded" at 182.722,3.532 h1.03
  text "v64h25m0mx0" at 195.657,3.532 h1.03
  text "176 Total" at 93.057,0.962 h1.03
  text ".Layer_Name" at 2.156,-34.306 h1.52
Special Dims:
  lines w0.25: 5.5,8.36 5.5,19.62 ; 26.72,8.36 26.72,19.62 ; 48,8.39 48,19.65 ; 69.25,8.35 69.25,19.61
  lines w0.254: 5.5,13.716 5.5,14.224 ; 7.024,13.461 5.5,13.97 ; 7.024,14.477 5.5,13.97 ; 8.736,13.967 5.5,13.97 ; 23.514,13.953 26.75,13.95 ; 25.226,13.443 26.75,13.95 ; 25.226,14.459 26.75,13.95 ; 26.75,13.696 26.75,14.204 ; 26.75,13.766 26.75,14.274 ; 28.274,13.511 26.75,14.02 ; 28.274,14.527 26.75,14.02 ; 29.986,14.017 26.75,14.02 ; 44.764,14.003 48,14 ; 46.476,13.493 48,14 ; 46.476,14.509 48,14 ; 49.524,13.491 48,14 ; 49.524,14.507 48,14 ; 51.236,13.997 48,14 ; 66.014,13.983 69.25,13.98 ; 67.726,13.473 69.25,13.98 ; 67.726,14.489 69.25,13.98 ; 69.25,13.726 69.25,14.234 ; 48,13.746 48,14.254 48,13.746
  text "21.25001mm" at 30.239,13.103 h1.52 r359.95
  text "21.25001mm" at 51.489,13.083 h1.52 r359.95
  text "21.25001mm" at 8.989,13.053 h1.52 r359.95
  text ".Layer_Name" at 2.156,-34.306 h1.52

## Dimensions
0,0 to 75,0 on M2 Board Dimensions
0,0 to 0,58 on M2 Board Dimensions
